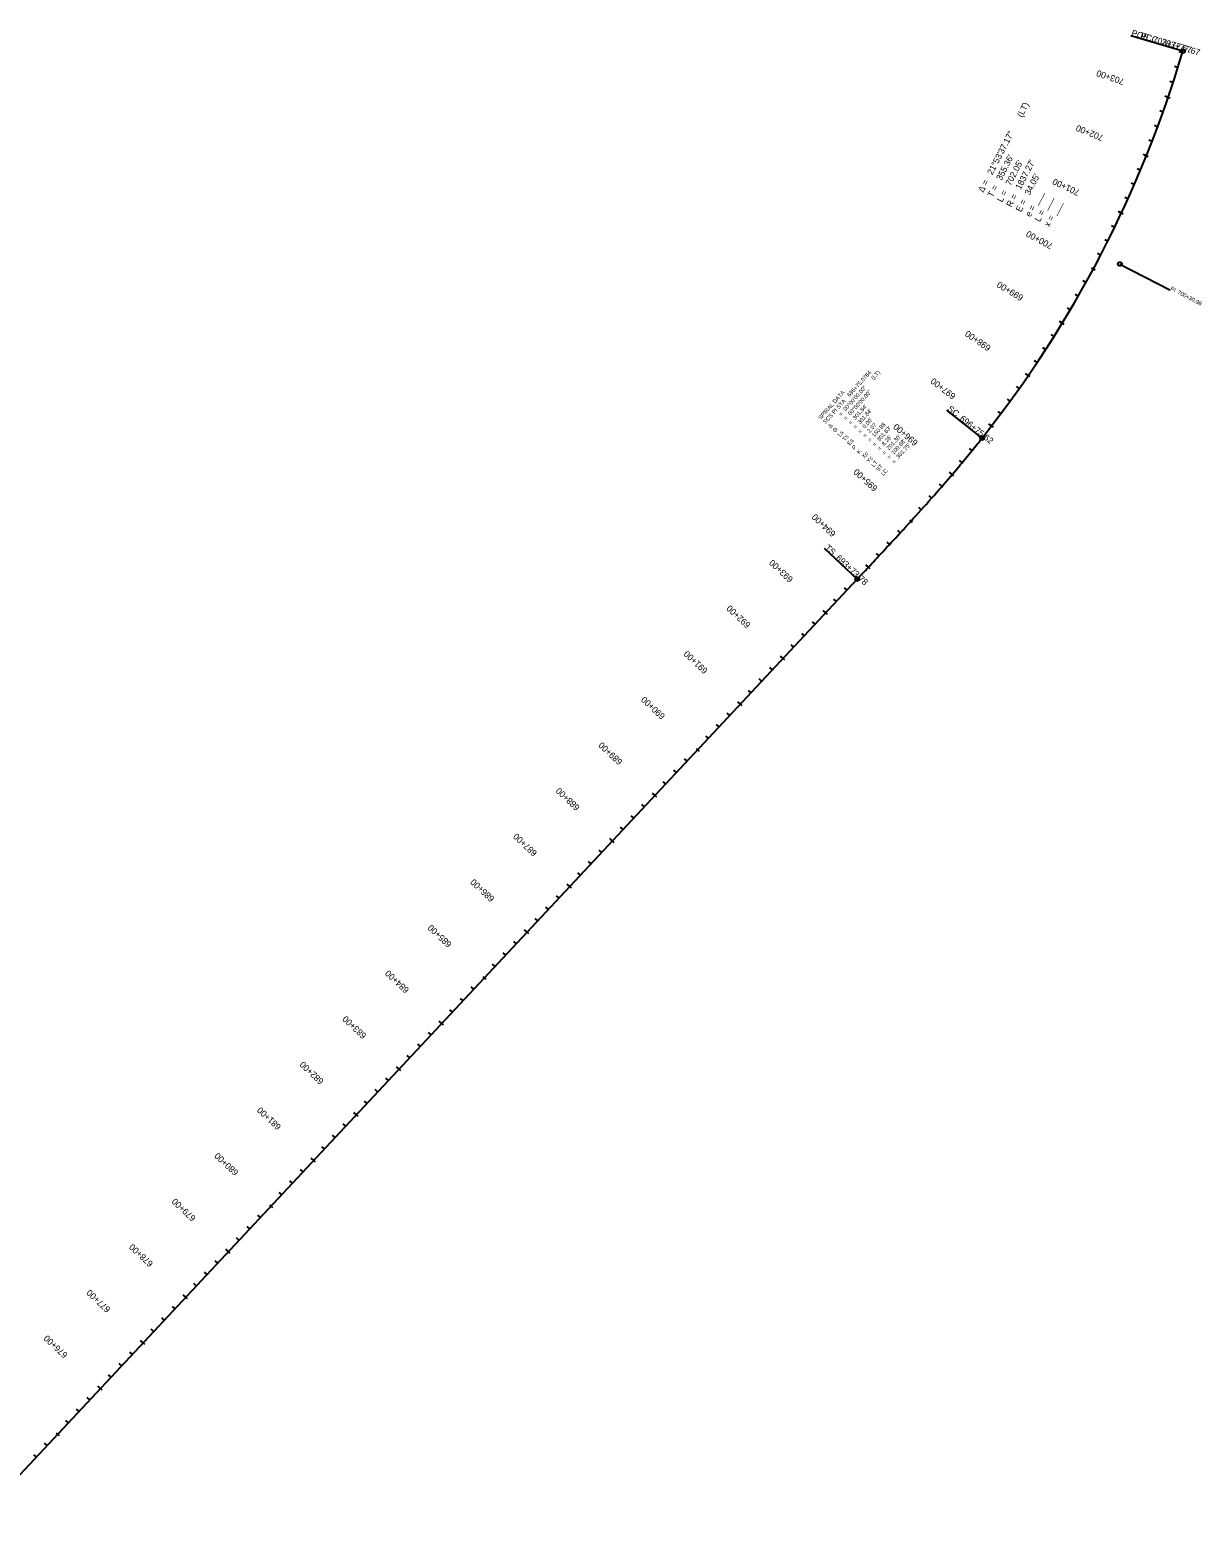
# Model space of a CAD drawing. Extents: x 11276213 to 11292489, y 9492633 to 9513914.
# Drawn here: x 11290614 to 11292489, y 9511532 to 9513914 of the extents above; entities that cross this region are included whole.
import ezdxf

# ---------------------------------------------------------------- set-up
doc = ezdxf.new("R2010")
doc.units = 0
for name, color, linetype in [('Alignment', 7, 'Continuous'), ('TextAlignment', 7, 'Continuous'), ('TextAlignmentLrg', 7, 'Continuous'), ('TextAlignmentSml', 7, 'Continuous')]:
    doc.layers.add(name, color=color, linetype=linetype)

msp = doc.modelspace()

# ---------------------------------------------------------------- linework, layer by layer
at = {"layer": 'Alignment'}
msp.add_line((11290532.5, 9511531.8), (11291938.3, 9513034.8), dxfattribs=at)
msp.add_arc((11290698, 9514401.4), 1837.3, 321.6206, 343.5143, dxfattribs=at)
msp.add_arc((11290698, 9514401.4), 1837.3, 321.6206, 343.5143, dxfattribs=at)
msp.add_open_spline([(11291938.3, 9513034.8), (11291944, 9513040.9), (11291955.5, 9513053.1), (11291978.4, 9513077.7), (11292006.9, 9513108.4), (11292040.7, 9513145.6), (11292074.1, 9513183.3), (11292101.3, 9513215.2), (11292122.6, 9513241.1), (11292133.1, 9513254.1), (11292138.3, 9513260.7)], degree=3, dxfattribs=at)
msp.add_open_spline([(11291938.3, 9513034.8), (11291944, 9513040.9), (11291955.5, 9513053.1), (11291978.4, 9513077.7), (11292006.9, 9513108.4), (11292040.7, 9513145.6), (11292074.1, 9513183.3), (11292101.3, 9513215.2), (11292122.6, 9513241.1), (11292133.1, 9513254.1), (11292138.3, 9513260.7)], degree=3, dxfattribs=at)
at = {"layer": 'TextAlignment'}
for p, q in [((11292459.8, 9513880), (11292376.4, 9513904.7)), ((11292459.8, 9513880), (11292390.7, 9513900.5)), ((11292358.9, 9513539.3), (11292438.8, 9513497.8)), ((11292138.3, 9513260.7), (11292081.9, 9513305.4)), ((11292138.3, 9513260.7), (11292081.9, 9513305.4)), ((11291938.3, 9513034.8), (11291885.7, 9513084))]:
    msp.add_line(p, q, dxfattribs=at)
for centre, radius in [((11292459.8, 9513880), 3.12), ((11292459.8, 9513880), 2.67), ((11292358.9, 9513539.3), 3.12), ((11292138.3, 9513260.7), 3.12), ((11292138.3, 9513260.7), 3.12), ((11291938.3, 9513034.8), 3.12)]:
    msp.add_circle(centre, radius, dxfattribs=at)
at = {"layer": 'TextAlignmentLrg'}
for p, q in [((11292436.2, 9513806), (11292431, 9513807.8)), ((11292401.2, 9513712.4), (11292396.2, 9513714.4)), ((11292361.2, 9513620.7), (11292356.3, 9513623.1)), ((11292313.6, 9513532.9), (11292319, 9513530)), ((11292266.5, 9513444.7), (11292261.9, 9513447.5)), ((11292212.2, 9513360.8), (11292207.7, 9513363.8)), ((11292153.3, 9513279.9), (11292149, 9513283.3)), ((11292090.3, 9513202.3), (11292086.1, 9513205.9)), ((11292021.8, 9513129.4), (11292026.3, 9513125.3)), ((11291956.2, 9513053.9), (11291952.2, 9513057.7)), ((11291887.9, 9512980.9), (11291883.9, 9512984.6)), ((11291819.6, 9512907.9), (11291815.6, 9512911.6)), ((11291751.3, 9512834.8), (11291747.3, 9512838.6)), ((11291680.7, 9512763.9), (11291685.2, 9512759.7)), ((11291614.7, 9512688.8), (11291610.7, 9512692.5)), ((11291546.4, 9512615.7), (11291542.4, 9512619.5)), ((11291478, 9512542.7), (11291474.1, 9512546.4)), ((11291409.7, 9512469.7), (11291405.7, 9512473.4)), ((11291339.2, 9512398.7), (11291343.7, 9512394.5)), ((11291273.1, 9512323.6), (11291269.1, 9512327.3)), ((11291204.8, 9512250.6), (11291200.8, 9512254.3)), ((11291136.5, 9512177.5), (11291132.5, 9512181.3)), ((11291068.2, 9512104.5), (11291064.2, 9512108.2)), ((11290997.6, 9512033.6), (11291002.1, 9512029.4)), ((11290931.6, 9511958.4), (11290927.6, 9511962.2)), ((11290863.3, 9511885.4), (11290859.3, 9511889.1)), ((11290795, 9511812.4), (11290791, 9511816.1)), ((11290726.6, 9511739.3), (11290722.7, 9511743.1)), ((11290656.1, 9511668.4), (11290660.6, 9511664.2))]:
    msp.add_line(p, q, dxfattribs=at)
at = {"layer": 'TextAlignmentSml'}
for p, q in [((11292459, 9513877.5), (11292453.8, 9513879)), ((11292451.7, 9513853.6), (11292446.5, 9513855.2)), ((11292444.1, 9513829.8), (11292438.9, 9513831.5)), ((11292433.3, 9513807), (11292439.1, 9513805.1)), ((11292427.9, 9513782.5), (11292422.8, 9513784.3)), ((11292419.3, 9513759), (11292414.2, 9513760.9)), ((11292410.4, 9513735.6), (11292405.3, 9513737.6)), ((11292398.4, 9513713.5), (11292404, 9513711.2)), ((11292391.7, 9513689.3), (11292386.6, 9513691.4)), ((11292381.8, 9513666.3), (11292376.8, 9513668.5)), ((11292371.7, 9513643.4), (11292366.7, 9513645.7)), ((11292358.4, 9513622), (11292364, 9513619.4)), ((11292350.4, 9513598.2), (11292345.5, 9513600.6)), ((11292339.3, 9513575.8), (11292334.5, 9513578.2)), ((11292328, 9513553.5), (11292323.1, 9513556)), ((11292313.6, 9513532.9), (11292319, 9513530)), ((11292304.3, 9513509.5), (11292299.5, 9513512.1)), ((11292279.4, 9513466.1), (11292274.7, 9513468.9)), ((11292292, 9513487.7), (11292287.3, 9513490.4)), ((11292263.9, 9513446.3), (11292269.2, 9513443.1)), ((11292253.4, 9513423.4), (11292248.8, 9513426.3)), ((11292239.9, 9513402.3), (11292235.4, 9513405.3)), ((11292226.2, 9513381.5), (11292221.7, 9513384.5)), ((11292209.7, 9513362.5), (11292214.7, 9513359)), ((11292197.9, 9513340.2), (11292193.4, 9513343.4)), ((11292168.4, 9513299.8), (11292164.1, 9513303.1)), ((11292183.3, 9513319.9), (11292178.9, 9513323.2)), ((11292150.9, 9513281.8), (11292155.7, 9513278.1)), ((11292137.9, 9513260.2), (11292133.6, 9513263.6)), ((11292122.3, 9513240.7), (11292118, 9513244.2)), ((11292106.4, 9513221.4), (11292102.2, 9513224.9)), ((11292073.9, 9513183.4), (11292069.8, 9513187)), ((11292087.9, 9513204.3), (11292092.6, 9513200.3)), ((11292057.5, 9513164.6), (11292053.4, 9513168.2)), ((11292040.8, 9513145.9), (11292036.8, 9513149.6)), ((11292007.2, 9513108.9), (11292003.2, 9513112.6)), ((11292021.8, 9513129.4), (11292026.3, 9513125.3)), ((11291990.3, 9513090.5), (11291986.3, 9513094.2)), ((11291973.3, 9513072.2), (11291969.3, 9513075.9)), ((11291939.1, 9513035.7), (11291935.1, 9513039.4)), ((11291954, 9513056), (11291958.4, 9513051.8)), ((11291922.1, 9513017.4), (11291918.1, 9513021.1)), ((11291905, 9512999.2), (11291901, 9513002.9)), ((11291885.7, 9512983), (11291890.1, 9512978.8)), ((11291853.7, 9512944.4), (11291849.8, 9512948.1)), ((11291870.8, 9512962.6), (11291866.8, 9512966.4)), ((11291836.7, 9512926.1), (11291832.7, 9512929.8)), ((11291817.4, 9512909.9), (11291821.8, 9512905.8)), ((11291785.4, 9512871.3), (11291781.4, 9512875.1)), ((11291802.5, 9512889.6), (11291798.5, 9512893.3)), ((11291768.4, 9512853.1), (11291764.4, 9512856.8)), ((11291749, 9512836.9), (11291753.5, 9512832.7)), ((11291717.1, 9512798.3), (11291713.1, 9512802)), ((11291734.2, 9512816.6), (11291730.2, 9512820.3)), ((11291700, 9512780.1), (11291696.1, 9512783.8)), ((11291680.7, 9512763.9), (11291685.2, 9512759.7)), ((11291665.9, 9512743.5), (11291661.9, 9512747.3)), ((11291631.7, 9512707), (11291627.8, 9512710.7)), ((11291648.8, 9512725.3), (11291644.8, 9512729)), ((11291612.4, 9512690.9), (11291616.9, 9512686.7)), ((11291597.6, 9512670.5), (11291593.6, 9512674.2)), ((11291563.4, 9512634), (11291559.4, 9512637.7)), ((11291580.5, 9512652.2), (11291576.5, 9512656)), ((11291544.1, 9512617.8), (11291548.6, 9512613.6)), ((11291529.3, 9512597.5), (11291525.3, 9512601.2)), ((11291495.1, 9512561), (11291491.1, 9512564.7)), ((11291512.2, 9512579.2), (11291508.2, 9512582.9)), ((11291475.8, 9512544.8), (11291480.3, 9512540.6)), ((11291461, 9512524.4), (11291457, 9512528.2)), ((11291426.8, 9512487.9), (11291422.8, 9512491.6)), ((11291443.9, 9512506.2), (11291439.9, 9512509.9)), ((11291407.5, 9512471.8), (11291412, 9512467.6)), ((11291392.7, 9512451.4), (11291388.7, 9512455.1)), ((11291375.6, 9512433.1), (11291371.6, 9512436.9)), ((11291339.2, 9512398.7), (11291343.7, 9512394.5)), ((11291358.5, 9512414.9), (11291354.5, 9512418.6)), ((11291324.3, 9512378.4), (11291320.4, 9512382.1)), ((11291307.3, 9512360.1), (11291303.3, 9512363.8)), ((11291270.9, 9512325.7), (11291275.4, 9512321.5)), ((11291290.2, 9512341.9), (11291286.2, 9512345.6)), ((11291256, 9512305.3), (11291252.1, 9512309.1)), ((11291239, 9512287.1), (11291235, 9512290.8)), ((11291221.9, 9512268.8), (11291217.9, 9512272.5)), ((11291187.7, 9512232.3), (11291183.7, 9512236)), ((11291202.6, 9512252.7), (11291207, 9512248.5)), ((11291170.7, 9512214), (11291166.7, 9512217.8)), ((11291153.6, 9512195.8), (11291149.6, 9512199.5)), ((11291119.4, 9512159.3), (11291115.4, 9512163)), ((11291134.3, 9512179.6), (11291138.7, 9512175.4)), ((11291102.3, 9512141), (11291098.4, 9512144.7)), ((11291085.3, 9512122.8), (11291081.3, 9512126.5)), ((11291051.1, 9512086.2), (11291047.1, 9512090)), ((11291066, 9512106.6), (11291070.4, 9512102.4)), ((11291034, 9512068), (11291030, 9512071.7)), ((11291017, 9512049.7), (11291013, 9512053.4)), ((11290982.8, 9512013.2), (11290978.8, 9512016.9)), ((11290997.6, 9512033.6), (11291002.1, 9512029.4)), ((11290965.7, 9511994.9), (11290961.7, 9511998.7)), ((11290948.6, 9511976.7), (11290944.7, 9511980.4)), ((11290914.5, 9511940.2), (11290910.5, 9511943.9)), ((11290929.3, 9511960.5), (11290933.8, 9511956.3)), ((11290897.4, 9511921.9), (11290893.4, 9511925.6)), ((11290880.3, 9511903.7), (11290876.3, 9511907.4)), ((11290861, 9511887.5), (11290865.5, 9511883.3)), ((11290829.1, 9511848.9), (11290825.1, 9511852.6)), ((11290846.2, 9511867.1), (11290842.2, 9511870.9)), ((11290812, 9511830.6), (11290808, 9511834.4)), ((11290792.7, 9511814.5), (11290797.2, 9511810.3)), ((11290760.8, 9511775.8), (11290756.8, 9511779.6)), ((11290777.9, 9511794.1), (11290773.9, 9511797.8)), ((11290743.7, 9511757.6), (11290739.7, 9511761.3)), ((11290724.4, 9511741.4), (11290728.9, 9511737.2)), ((11290692.5, 9511702.8), (11290688.5, 9511706.5)), ((11290709.6, 9511721.1), (11290705.6, 9511724.8)), ((11290675.4, 9511684.6), (11290671.4, 9511688.3)), ((11290656.1, 9511668.4), (11290660.6, 9511664.2)), ((11290624.2, 9511629.8), (11290620.2, 9511633.5)), ((11290641.3, 9511648), (11290637.3, 9511651.8))]:
    msp.add_line(p, q, dxfattribs=at)

# ---------------------------------------------------------------- texts
at = {"layer": 'TextAlignment'}
for s, height, rotation, p in [('POE ', 10.02, 343.5143, (11292376.4, 9513904.9)), ('PCC', 10.02, 343.5143, (11292390.8, 9513900.7)), ('703+77.67', 10.02, 343.5143, (11292410.9, 9513894.7)), ('703+77.67', 10.02, 343.5143, (11292424.4, 9513890.7)), (' (LT)', 10.02, 62.5674, (11292200.7, 9513769.9)), ('21°53\'37.17"', 10.02, 62.5674, (11292154.6, 9513681.1)), ("355.36'", 10.02, 62.5674, (11292169.1, 9513672.1)), ("702.05'", 10.02, 62.5674, (11292184, 9513663.7)), ("1837.27'", 10.02, 62.5674, (11292199.9, 9513657.5)), ("34.05'", 10.02, 62.5674, (11292214.5, 9513648.6)), ('Δ = ', 10.02, 62.5674, (11292140, 9513653)), ('T = ', 10.02, 62.5674, (11292155.1, 9513645.1)), ('L = ', 10.02, 62.5674, (11292170.2, 9513637.3)), ('R = ', 10.02, 62.5674, (11292185.3, 9513629.4)), ('E = ', 10.02, 62.5674, (11292200.4, 9513621.6)), ('e = ___ ', 10.02, 62.5674, (11292215.6, 9513613.7)), ('L = ___', 10.02, 62.5674, (11292230.7, 9513605.9)), ('x = ___', 10.02, 62.5674, (11292245.8, 9513598)), ('PI ', 6.48, 332.5674, (11292438.9, 9513497.9)), ('700+30.98', 6.48, 332.5674, (11292450.3, 9513492)), ('695+75.0784', 6.48, 48.0908, (11291926.3, 9513326)), (' (LT)', 6.48, 48.0908, (11291962.9, 9513351.3)), ('SPIRAL DATA', 6.48, 48.0908, (11291880, 9513289.9)), ('00°00\'00.00"', 6.48, 48.0908, (11291919.7, 9513303.2)), ('00°00\'00.00"', 6.48, 48.0908, (11291927.5, 9513296.2)), ('SCS PI STA ', 6.48, 48.0908, (11291887.7, 9513282.9)), ('= ', 6.48, 48.0908, (11291912.7, 9513295.3)), ("301.84'", 6.48, 48.0908, (11291935.2, 9513289.3)), ("301.84'", 6.48, 48.0908, (11291942.9, 9513282.4)), ('SC', 10.02, 321.6206, (11292082, 9513305.6)), ('SC', 10.02, 321.6206, (11292082, 9513305.6)), ('Δ', 6.48, 48.0908, (11291895.4, 9513276)), ('= ', 6.48, 48.0908, (11291920.4, 9513288.4)), ('= ', 6.48, 48.0908, (11291928.1, 9513281.5)), ('= ', 6.48, 48.0908, (11291935.8, 9513274.5)), ("0.00'", 6.48, 48.0908, (11291950.6, 9513275.5)), ('2.07', 6.48, 48.0908, (11291958.3, 9513268.5)), ('150.88', 6.48, 48.0908, (11291966, 9513261.6)), ("301.63'", 6.48, 48.0908, (11291973.7, 9513254.7)), ('696+75.62', 10.02, 321.6206, (11292101.4, 9513290.2)), ('696+75.62', 10.02, 321.6206, (11292101.4, 9513290.2)), ('Θ ', 6.48, 48.0908, (11291903.1, 9513269.1)), ('Ls', 6.48, 48.0908, (11291910.8, 9513262.2)), ('Ts', 6.48, 48.0908, (11291918.5, 9513255.2)), ('Es', 6.48, 48.0908, (11291926.2, 9513248.3)), ('= ', 6.48, 48.0908, (11291943.6, 9513267.6)), ('= ', 6.48, 48.0908, (11291951.3, 9513260.7)), ('= ', 6.48, 48.0908, (11291959, 9513253.8)), ("8.26'", 6.48, 48.0908, (11291981.5, 9513247.8)), ("201.30'", 6.48, 48.0908, (11291989.2, 9513240.8)), ("100.68'", 6.48, 48.0908, (11291996.9, 9513233.9)), ('P', 6.48, 48.0908, (11291934, 9513241.4)), ('K', 6.48, 48.0908, (11291941.7, 9513234.5)), ('Xc', 6.48, 48.0908, (11291949.4, 9513227.5)), ('Yc', 6.48, 48.0908, (11291957.1, 9513220.6)), ('= ', 6.48, 48.0908, (11291966.7, 9513246.8)), ('= ', 6.48, 48.0908, (11291974.4, 9513239.9)), ('= ', 6.48, 48.0908, (11291982.1, 9513233)), ('= ', 6.48, 48.0908, (11291989.9, 9513226.1)), ("301.75'", 6.48, 48.0908, (11292004.6, 9513227)), ('LT', 6.48, 48.0908, (11291964.8, 9513213.7)), ('ST ', 6.48, 48.0908, (11291972.5, 9513206.8)), ('LC', 6.48, 48.0908, (11291980.3, 9513199.8)), ('= ', 6.48, 48.0908, (11291997.6, 9513219.1)), ('TS', 10.02, 316.9142, (11291885.8, 9513084.1)), ('693+73.78', 10.02, 316.9142, (11291903.4, 9513067.7))]:
    msp.add_text(s, height=height, rotation=rotation, dxfattribs=at).set_placement(p)
at = {"layer": 'TextAlignmentLrg'}
for s, rotation, p in [('700+00', 151.7365, (11292252.6, 9513571.4)), ('695+00', 137.7371, (11291972, 9513181.6)), ('690+00', 136.9142, (11291631.7, 9512816.7)), ('685+00', 136.9142, (11291290.1, 9512451.6)), ('680+00', 136.9142, (11290948.6, 9512086.4))]:
    msp.add_text(s, height=10.2, rotation=rotation, dxfattribs=at).set_placement(p)
at = {"layer": 'TextAlignmentSml'}
for s, rotation, p in [('703+00', 161.0921, (11292366.9, 9513835.2)), ('702+00', 157.9736, (11292333.6, 9513745.2)), ('701+00', 154.855, (11292295.5, 9513657.2)), ('700+00', 151.7365, (11292252.6, 9513571.4)), ('699+00', 148.618, (11292205.2, 9513488.1)), ('698+00', 145.4994, (11292153.3, 9513407.4)), ('697+00', 142.3809, (11292097, 9513329.7)), ('696+00', 139.5578, (11292036.5, 9513254.9)), ('695+00', 137.7371, (11291972, 9513181.6)), ('694+00', 136.9497, (11291904.9, 9513108.9)), ('693+00', 136.9142, (11291836.6, 9513035.8)), ('692+00', 136.9142, (11291768.3, 9512962.8)), ('691+00', 136.9142, (11291700, 9512889.8)), ('690+00', 136.9142, (11291631.7, 9512816.7)), ('689+00', 136.9142, (11291563.4, 9512743.7)), ('688+00', 136.9142, (11291495.1, 9512670.7)), ('687+00', 136.9142, (11291426.8, 9512597.7)), ('686+00', 136.9142, (11291358.4, 9512524.6)), ('685+00', 136.9142, (11291290.1, 9512451.6)), ('684+00', 136.9142, (11291221.8, 9512378.6)), ('683+00', 136.9142, (11291153.5, 9512305.5)), ('682+00', 136.9142, (11291085.2, 9512232.5)), ('681+00', 136.9142, (11291016.9, 9512159.5)), ('680+00', 136.9142, (11290948.6, 9512086.4)), ('679+00', 136.9142, (11290880.3, 9512013.4)), ('678+00', 136.9142, (11290812, 9511940.4)), ('677+00', 136.9142, (11290743.7, 9511867.3)), ('676+00', 136.9142, (11290675.3, 9511794.3))]:
    msp.add_text(s, height=10.2, rotation=rotation, dxfattribs=at).set_placement(p)

doc.saveas('drawing.dxf')
